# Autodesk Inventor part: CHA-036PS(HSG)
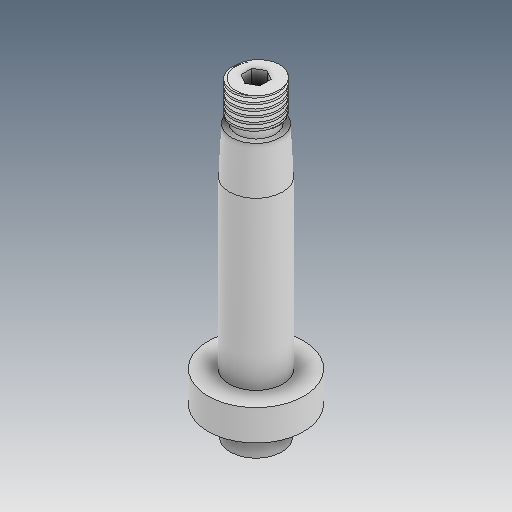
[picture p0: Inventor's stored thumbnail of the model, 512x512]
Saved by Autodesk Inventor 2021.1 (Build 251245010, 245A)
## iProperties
Created: 2021-05
Part Number: CHA-036PS(HSG)
Material: Ogólny
Document SubType Name: Modeling
Designer: user
Density: 1 g/cm^3
Appearance: Domyślna
Author: user
Revision Number: ÈÎºÎ
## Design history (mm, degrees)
feature "µ¹½Ç1"
node "Bryła1"
